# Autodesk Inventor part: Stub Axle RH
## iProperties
Shininess: 70.0
Angle Display Precision: 2
Document Length Units: 11269
Document Angle Units: 11279
Document Time Units: 11290
Document Mass Units: 11283
Document Length Units Precision: 3
Document Angle Units Precision: 2
Compacted: True
Created: 2001-08
Part Number: Stub Axle RH
Document SubType Name: Sheet Metal
Designer: Martin Budgell
Density: 0.0
Volumn: 0.0
Area: 0.0
PropertySet Name: Model Information
Control State: 0
Master: False
Checked Out: False
Author: Martin Budgell
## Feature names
1. Hole1
2. Corner Chamfer1
3. Plate1
4. Bend1
5. Cut1
